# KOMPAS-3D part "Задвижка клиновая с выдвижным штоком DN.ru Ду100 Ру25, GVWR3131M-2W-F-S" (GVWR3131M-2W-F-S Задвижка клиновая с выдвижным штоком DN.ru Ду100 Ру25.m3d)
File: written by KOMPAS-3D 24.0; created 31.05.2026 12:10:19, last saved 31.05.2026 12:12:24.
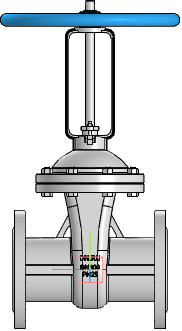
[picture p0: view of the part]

Document properties: Автор: R2D2; Полное имя файла: E:\Работа\Зайцев\GVWR3131M-2W-F-S Задвижка клиновая 30нж64нж DN.ru  Ду50-150 Ру25\исходные данные\DN100\dn100\GVWR3131M-2W-F-S Задвижка клиновая с выдвижным штоком DN.ru Ду100 Ру25.m3d

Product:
- Part/product: Задвижка клиновая с выдвижным штоком DN.ru Ду100 Ру25  | designation GVWR3131M-2W-F-S
    Масса: 29
    Раздел спецификации: Прочие изделия
    Примечание: D040-07876

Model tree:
1. Операция без истории:1

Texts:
  GVWR3131M-2W-F-S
